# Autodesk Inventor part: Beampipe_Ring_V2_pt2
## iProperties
Shininess: 64.0
Length Units: 11269
Angle Units: 11279
Time Units: 11290
Mass Units: 11283
Length Display Precision: 3
Angle Display Precision: 2
Compacted: True
Part Number: Beampipe_Ring_V2_pt2
Document SubType Name: Modeling
Created: 2004-08
Designer: John Blackburn
Manufacturer: Standard
Standards Organization: Custom
Material: Aluminum-6061
Density: 0.0
Volumn: 0.0
Area: 0.0
PropertySet Name: Model Information
Control State: 0
Master: False
Checked Out: False
Author: John Blackburn
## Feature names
1. Extrusion1
2. Extrusion3
3. Split1
4. Hole4
5. Hole5
6. Hole6
7. Circular Pattern1
8. Hole8
9. Hole9
